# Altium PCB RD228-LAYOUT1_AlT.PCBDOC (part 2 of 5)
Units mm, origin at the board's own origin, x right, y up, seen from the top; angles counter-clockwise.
Board outline 130 x 73 mm, 4 copper layers (TOP, Mid-Layer 1, Mid-Layer 2, BOTTOM), stack 0.711 mm thick; 225 components, 171 nets, 818 pads, 538 vias.
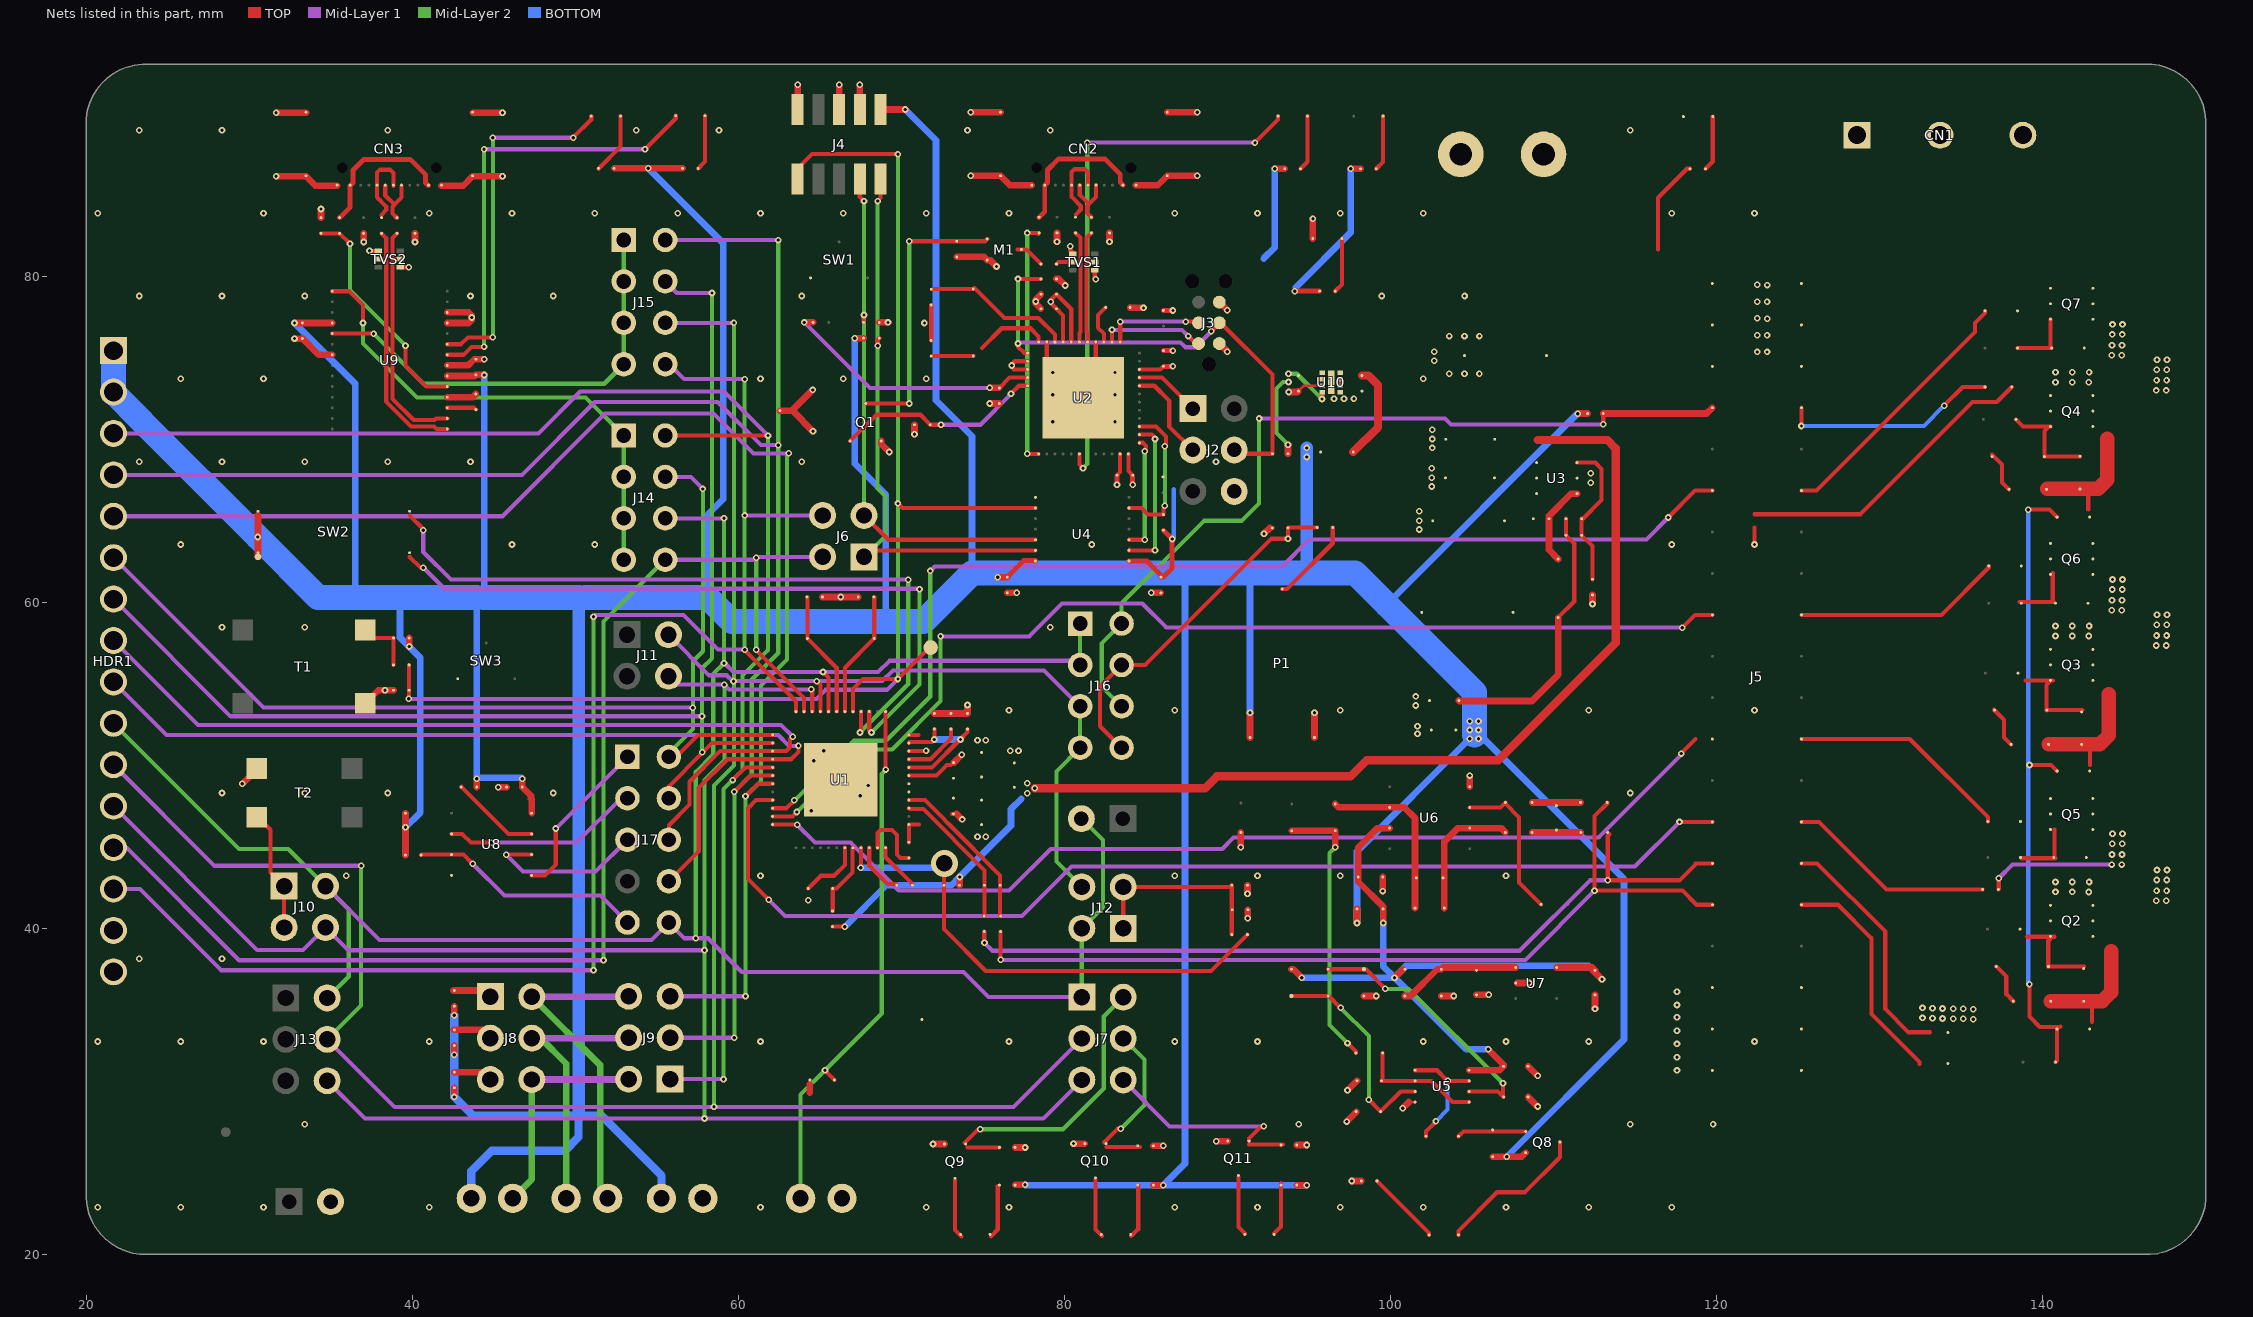
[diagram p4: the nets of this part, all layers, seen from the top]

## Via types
v1: diameter 0.406, hole 0.203, TOP to BOTTOM, tented both sides, 533 vias
v2: diameter 6, hole 4.2, TOP to BOTTOM, 4 vias
v3: diameter 1.651, hole 1, TOP to BOTTOM, 1 vias

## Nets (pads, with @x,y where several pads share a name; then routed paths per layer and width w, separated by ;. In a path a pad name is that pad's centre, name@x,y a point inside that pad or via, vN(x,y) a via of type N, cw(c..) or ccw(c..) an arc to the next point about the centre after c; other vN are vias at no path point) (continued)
GND: ?.2 C1.1 C2.1 C3.1 C4.1 C5.1 C6.1 C7.1 C8.1 C9.1 C10.1 C11.1 C12.1 C13.1 C15.1 C17.2 C18.2 C19.2 C22.1 C23.2 C24.1 C25.1 C26.1 C29.2 C30.2 C32.2 C33.2 C34.2 C35.2 C36.2 C37.2 C38.2 C40.1 C41.1 C42.2 C44.1 C46.1 C52.1 C53.1 C55.1 C57.1 C58.1 C59.1 C60.1 C61.1 CN2.1 CN2.2 CN2.3 CN2.4 CN2.A1B12 CN2.B1A12 CN3.1 CN3.2 CN3.3 CN3.4 CN3.A1B12 CN3.B1A12 D3.2 HDR1.15 HDR1.16 J2.6 J3.5 J4.3 J4.5 J4.9 J5.35 J5.37 J5.39 J18.2 LD1.1 LD3.1 P1.3 Q1.2 Q9.2 Q10.2 Q11.2 R5.1 R10.1 R17.1 R18.1 R21.2 R35.1 R36.1 R55.2 R58.1 R60.1 R61.1 R62.1 R65.2 R67.2 R69.2 R85.1 RT1.2 SW1.1 SW3.1 T1.1 T2.1 TB1.1 TB2.2 TB5.2 TP2.1 TP3.1 TVS1.1 TVS1.4 TVS2.1 TVS2.4 U1.19 U1.31 U1.34 U1.36 U1.49 U2.2 U2.3 U2.24 U2.41 U2.47 U2.49 U3.2 U4.9 U5.4 U6.4 U7.2 U8.4 U9.7 U9.18 U9.21 U9.25 U9.26 U10.3 U10.5 U10.9 | length 131.2
  TOP w0.152: C40.1@94.35,72.945 94.684,73.279 U10.3@95.815,73.279 ; 101.122,29.346 U5.4@101.508,29.346
  TOP w0.254: v1(37.377,81.553) 37.385,81.545 TVS2.1@37.922,81.545 ; TVS2.4@39.272,80.545 v1(39.79,80.545) ; C44.1@64.288,42.437 65.075,43.225 65.864,43.225 66.533,43.894 U1.19@66.533,44.942 ; U1.31@70.458,49.367 72.146,49.367 72.785,50.006 73.014,50.006 ; U1.34@70.458,50.867 71.487,50.867 v1(71.515,50.895) ; U1.36@70.458,51.867 71.039,51.867 ; C12.1@71.828,76.055 C13.1@71.828,78.228 ; C7.1@71.989,53.179 C7.1@72.023,53.179 ; C3.1@73.103,47.022 C3.1@73.192,47.022 73.381,47.022 ; C5.1@73.195,50.167 C5.1@73.225,50.167 ; U2.3@77.738,74.276 76.913,74.276 76.773,74.416 v1(76.773,74.517) 76.773,74.594 76.955,74.776 U2.2@77.738,74.776 ; U2.47@78.918,75.956 78.918,74.776 79.448,74.246 U2.49@81.168,72.526 81.918,73.276 U2.41@81.918,75.956 ; U2.24@83.918,69.096 83.918,68.055 C35.2@84.187,67.786 ; 92.597,64.561 C17.2@92.752,64.561 ; U6.4@104.856,48.686 U6.4@104.865,48.694 ; v1(122.319,63.538) 122.319,64.59 ; 122.319,65.399 128.817,65.399 135.694,72.276 137.175,72.276 RT1.2@138.096,73.197 RT1.2@138.088,73.204
  TOP w0.279: v1@80.354,81.807 80.354,81.579 80.503,81.43 TVS1.1@80.503,81.359 ; v1@81.853,79.876 TVS1.4@81.853,80.359
  TOP w0.305: v1(84.187,67.202) C35.2@84.187,67.786 ; C36.2@86.069,75.429 v1(86.653,75.429)
  TOP w0.406: v1(29.58,48.867) 29.584,48.867 30.469,49.752 T2.1@30.469,49.805 T2.1@30.469,50.059 ; v1(31.652,86.12) 33.487,86.12 34.062,85.544 CN3.B1A12@35.397,85.544 ; v1(31.652,90.02) CN3.4@33.487,90.02 ; v1(32.78,76.168) 33.26,76.168 C29.2@33.263,76.171 34.26,75.173 U9.7@35.097,75.173 ; R17.1@34.406,83.583 v1(34.406,84.116) ; v1(37.022,82.089) R61.1@37.022,82.623 ; T1.1@37.114,53.802 37.917,54.604 v1(38.335,54.604) C33.2@38.853,54.604 ; v1(40.171,82.089) R62.1@40.171,82.623 ; CN3.A1B12@41.797,85.544 43.131,85.544 43.707,86.12 v1(45.541,86.12) ; U9.18@42.147,72.572 43.708,72.572 C32.2@43.905,72.77 ; U9.21@42.147,74.523 43.428,74.523 43.808,74.903 C30.2@43.905,74.903 44.409,74.903 v1(44.413,74.898) ; U9.25@42.147,77.124 43.464,77.124 43.651,77.311 v1(43.651,77.464) 43.651,77.591 43.468,77.774 U9.26@42.147,77.774 ; CN3.1@43.707,90.02 v1(45.541,90.02) ; v1(45.272,48.66) C26.1@45.79,48.66 ; TP2.1@62.549,71.749 63.285,71.749 ; J4.9@63.641,90.215 v1(63.641,91.735) ; 64.383,29.927 64.383,30.445 ; v1(64.555,73.019) 63.285,71.749 ; v1(64.583,70.479) 63.313,71.749 63.285,71.749 ; C10.1@65.162,60.319 C9.1@67.352,60.319 ; J4.5@66.181,90.215 v1(66.181,91.735) ; J4.3@67.451,90.215 v1(67.451,91.735) ; R21.2@68.642,77.159 v1(69.176,77.159) ; Q1.2@68.761,69.888 68.761,69.703 v1(69.254,69.209) ; v1(70.806,70.301) R5.1@70.806,70.885 ; v1(71.942,26.774) Q9.2@72.643,26.774 ; C7.1@72.023,53.179 C6.1@73.039,53.179 C8.1@74.055,53.179 v1(74.055,53.697) ; C5.1@73.225,50.167 v1(73.699,50.641) ; 73.381,47.022 v1(73.725,46.679) ; v1(74.248,86.152) CN2.3@76.082,86.152 76.658,85.576 CN2.B1A12@77.992,85.576 ; v1(74.248,90.052) CN2.4@76.082,90.052 ; v1(75.427,72.183) C34.2@76.011,72.183 ; C18.2@76.493,60.575 v1(77.078,60.575) ; R65.2@76.973,26.562 v1(77.586,26.562) ; C37.2@78.553,77.997 78.246,78.305 v1(78.246,78.442) 78.246,78.579 C38.2@78.553,78.886 ; ?.2@79.513,79.826 79.643,79.826 v1(80.049,79.42) ; v1(79.541,82.115) R35.1@79.541,82.648 ; v1(80.553,26.799) Q10.2@81.254,26.799 ; v1(82.767,82.115) R36.1@82.767,82.648 ; C11.1@84.025,78.073 84.051,78.048 v1(84.85,78.048) ; CN2.A1B12@84.392,85.576 85.727,85.576 CN2.2@86.302,86.152 v1(88.137,86.152) ; v1(85.333,60.575) C19.2@85.917,60.575 ; R67.2@85.454,26.664 v1(86.067,26.664) ; CN2.1@86.302,90.052 v1(88.137,90.052) ; v1(89.316,26.952) Q11.2@90.017,26.952 ; J3.5@89.498,78.404 v1(89.994,77.908) ; v1(90.819,44.977) C55.1@90.819,45.881 ; v1(91.223,42.122) C46.1@91.223,42.641 ; v1(91.251,40.621) R85.1@91.251,41.139 ; v1(92.241,64.205) 92.597,64.561 ; v1(93.765,72.892) 94.296,72.892 C40.1@94.35,72.945 ; R69.2@94.245,26.715 v1(94.858,26.715) ; LD3.1@95.239,82.3 v1(95.239,83.512) ; P1.3@95.334,51.705 v1(95.334,53.226) ; v1(97.309,28.15) 97.892,28.733 C57.1@97.892,28.763 ; v1(97.36,30.068) C59.1@97.943,30.652 ; v1(97.626,24.505) R55.2@98.21,24.505 ; R60.1@98.363,35.851 v1(99.118,35.851) ; v1(99.519,42.285) C52.1@99.519,43.148 ; v1(100.75,28.975) 101.122,29.346 ; R58.1@103.113,35.851 v1(103.867,35.851) ; U6.4@104.865,48.694 v1(104.865,49.367) ; C61.1@105.272,35.921 v1(106.026,35.921) ; U7.2@107.761,36.646 v1(108.516,36.646) ; C58.1@108.435,29.661 v1(109.018,29.078) ; C53.1@108.435,31.541 v1(109.018,30.957) ; v1(112.384,59.887) R10.1@112.384,60.448 ; v1(112.536,35.058) C60.1@112.536,35.921
  other v1: 20.719,22.898 25.799,22.898 30.879,22.898 41.039,22.898 61.359,22.898 71.519,22.898 76.599,22.898 86.759,22.898 91.839,22.898 96.919,22.898 101.999,22.898 107.079,22.898 112.159,22.898 117.239,22.898 33.419,27.978 94.379,27.978 114.699,27.978 119.779,27.978 117.565,31.287 117.565,32.099 117.565,32.912 20.719,33.058 25.799,33.058 30.879,33.058 41.039,33.058 61.359,33.058 76.599,33.058 86.759,33.058 91.839,33.058 101.999,33.058 107.079,33.058 112.159,33.058 122.319,33.058 117.565,33.725 117.565,34.538 117.565,35.3 117.565,36.113 23.259,38.138 28.339,38.138 64.288,41.726 35.959,43.218 61.359,43.218 86.759,43.218 91.839,43.218 96.919,43.218 107.079,43.218 74.665,45.612 75.173,45.612 64.479,47.212 67.476,48.127 28.339,48.298 33.419,48.298 38.499,48.298 48.659,48.298 114.699,48.298 67.959,48.762 64.632,50.286 65.241,50.895 76.671,50.895 77.179,50.895 74.665,51.53 75.173,51.53 101.65,51.937 101.65,52.394 76.599,53.378 86.759,53.378 96.919,53.378 112.159,53.378 122.319,53.378 101.538,53.664 101.538,54.223 28.339,58.458 33.419,58.458 79.139,58.458 66.283,60.319 25.799,63.538 46.119,63.538 51.199,63.538 81.679,63.538 117.239,63.538 101.754,64.459 101.754,65.002 101.754,65.577 102.53,67.097 112.282,67.329 102.53,67.64 112.282,67.913 102.53,68.214 23.259,68.618 28.339,68.618 33.419,68.618 38.499,68.618 43.579,68.618 63.899,68.618 89.299,68.618 102.554,69.463 102.554,70.006 102.554,70.58 79.287,71.063 83.097,71.063 96.534,72.485 97.144,72.485 97.753,72.485 79.287,72.714 83.097,72.714 25.799,73.698 30.879,73.698 61.359,73.698 66.439,73.698 71.519,73.698 101.999,73.698 103.595,74.009 104.535,74.009 105.449,74.009 79.287,74.086 83.097,74.086 102.679,74.804 102.679,75.363 103.595,76.321 104.535,76.321 105.449,76.321 71.413,77.124 23.259,78.778 28.339,78.778 33.419,78.778 43.579,78.778 48.659,78.778 63.899,78.778 99.459,78.778 104.539,78.778 81.919,79.81 80.354,81.833 20.719,83.858 30.879,83.858 41.039,83.858 46.119,83.858 51.199,83.858 56.279,83.858 61.359,83.858 66.439,83.858 71.519,83.858 76.599,83.858 86.759,83.858 91.839,83.858 96.919,83.858 101.999,83.858 117.239,83.858 122.319,83.858 23.259,88.938 28.339,88.938 38.499,88.938 53.739,88.938 58.819,88.938 74.059,88.938 79.139,88.938 114.699,88.938
HALL-U: J8.6 J9.2 TB3.2 | length 13.7
  Mid-Layer 1 w0.406: J8.6@47.334,30.728 53.252,30.728 J9.2@53.278,30.753
  Mid-Layer 2 w0.406: TB3.2@46.166,23.438 47.334,24.606 J8.6@47.334,30.728
HALL-V: J8.4 J9.4 TB4.1 | length 17
  Mid-Layer 1 w0.406: J8.4@47.334,33.268 53.252,33.268 J9.4@53.278,33.293
  Mid-Layer 2 w0.406: J8.4@47.334,33.268 47.868,33.268 49.442,31.693 TB4.1@49.442,23.438
HALL-W: J8.2 J9.6 TB4.2 | length 20.2
  Mid-Layer 1 w0.406: J8.2@47.334,35.808 53.252,35.808 J9.6@53.278,35.833
  Mid-Layer 2 w0.406: J8.2@47.334,35.808 51.525,31.617 51.525,23.895 TB4.2@51.982,23.438
I_LIMIT_H: C57.2 pad.@93.918,35.851 R57.1 R59.2 U5.3 | length 13.3
  TOP w0.254: R57.1@93.918,35.851 R59.2@96.178,35.851 96.211,35.851 v1(96.94,35.122) ; v1(98.668,29.487) C57.2@99.392,28.763 100.626,29.996 U5.3@101.508,29.996
  Mid-Layer 2 w0.254: v1(96.94,35.122) 98.668,33.395 v1(98.668,29.487)
I_LIMIT_L: C58.2 pad.@98.363,37.492 R59.1 R60.2 U5.6 | length 16.7
  TOP w0.254: R59.1@96.178,37.492 R60.2@98.363,37.492 98.483,37.492 v1(99.684,36.29) ; U5.6@104.818,29.996 106.599,29.996 C58.2@106.897,29.698 ; v1(106.897,30.499) C58.2@106.897,29.698 ; C58.2@106.935,29.661 C58.2@106.897,29.698
  Mid-Layer 2 w0.254: v1(99.684,36.29) 101.106,36.29 v1(106.897,30.499)
I_MEAS: R46.2 R47.1 R50.1 | length 17.1
  TOP w0.254: v1(97.36,32.963) 97.873,32.45 R50.1@97.873,32.353
  TOP w0.406: R47.1@93.943,45.986 R46.2@96.61,45.986 v1(96.61,44.964)
  Mid-Layer 2 w0.254: v1(96.61,44.964) 96.255,44.608 96.255,34.068 v1(97.36,32.963)
IO0: HDR1.3 J9.1 J14.2 U1.5 | length 95.3
  TOP w0.254: J14.2@55.513,70.225 v1@61.838,70.225 ; v1(59.653,49.092) 60.429,49.867 U1.5@62.108,49.867
  Mid-Layer 1 w0.254: HDR1.3@21.68,70.352 47.741,70.352 50.306,72.917 59.12,72.917 v1(61.817,70.22) ; J9.1@55.818,30.753 v1(59.094,30.753)
  Mid-Layer 2 w0.254: v1(59.094,30.753) 59.094,48.533 v1(59.653,49.092) 60.263,49.702 60.263,55.508 61.812,57.057 v1@61.812,70.225
IO1: HDR1.4 J9.3 J15.2 U1.6 | length 107.4
  TOP w0.254: v1@59.755,48.367 60.755,49.367 U1.6@62.108,49.367
  Mid-Layer 1 w0.254: HDR1.4@21.68,67.812 46.725,67.812 51.195,72.282 58.739,72.282 61.385,69.636 v1(62.452,69.636) ; J15.2@55.513,82.214 v1@62.447,82.214 ; J9.3@55.818,33.293 v1(59.755,33.293)
  Mid-Layer 2 w0.254: v1(59.755,33.293) v1(59.755,48.381) 60.822,49.448 60.822,55.264 62.447,56.89 62.447,69.636 v1@62.447,82.214
  other v1: 62.452,82.209
IO2: HDR1.5 J9.5 U1.7 | length 86
  TOP w0.254: v1(60.441,48.101) 61.207,48.867 U1.7@62.108,48.867
  Mid-Layer 1 w0.254: HDR1.5@21.68,65.272 45.531,65.272 51.83,71.571 58.485,71.571 60.928,69.128 v1(63.087,69.128) ; J9.5@55.818,35.833 v1(60.441,35.833)
  Mid-Layer 2 w0.254: v1(60.441,35.833) v1(60.441,48.101) 61.38,49.041 61.38,54.883 62.981,56.483 62.981,69.031 v1@63.082,69.133
IO3: HDR1.6 J14.4 J17.2 U1.1 | length 66.2
  TOP w0.254: J17.2@55.742,50.514 56.173,50.514 57.526,51.867 U1.1@62.108,51.867
  Mid-Layer 1 w0.254: HDR1.6@21.68,62.732 30.875,53.537 v1(57.215,53.537) ; J14.4@55.513,67.685 57.088,67.685 v1(57.824,66.948)
  Mid-Layer 2 w0.254: J17.2@55.742,50.514 55.742,50.743 57.215,52.216 v1(57.215,53.537) 57.215,56.382 57.824,56.991 v1@57.824,66.923
IO4: HDR1.7 J15.4 J17.4 U1.2 | length 79.3
  TOP w0.254: J17.4@56.148,47.974 J17.4@55.742,47.974 55.742,48.711 57.805,50.774 58.398,51.367 U1.2@62.108,51.367
  Mid-Layer 1 w0.254: HDR1.7@21.68,60.192 28.868,53.004 v1(57.774,53.004) ; J15.4@55.513,79.674 56.224,78.962 v1(58.383,78.962)
  Mid-Layer 2 w0.254: v1@57.774,50.794 v1(57.774,53.004) 57.774,55.95 58.383,56.56 v1(58.383,78.962)
  other v1: 57.786,50.794
IO5: HDR1.8 J17.6 U1.3 | length 56
  TOP w0.254: J17.6@55.742,45.434 55.742,46.323 57.012,47.593 57.012,48.99 58.889,50.867 U1.3@62.108,50.867 62.939,50.867 63.179,51.107 63.179,51.602 v1(63.336,51.759)
  Mid-Layer 1 w0.254: HDR1.8@21.68,57.652 26.862,52.47 62.625,52.47 v1(63.336,51.759) v1@63.362,51.734
IO6: HDR1.9 J17.8 U1.4 | length 57.5
  TOP w0.254: J17.8@55.742,42.894 57.57,44.723 57.57,48.609 59.328,50.367 U1.4@62.108,50.367 63.243,50.367 63.687,50.812 v1(63.687,51.192)
  Mid-Layer 1 w0.254: HDR1.9@21.68,55.112 24.931,51.861 62.447,51.861 63.116,51.192 v1(63.687,51.192)
IO7: HDR1.10 J7.1 J10.2 J12.2 J13.2 J14.6 J16.1 J16.3 J17.10 J33.2 U1.44 | length 145.7
  TOP w0.254: v1(65.19,55.721) 65.533,55.379 U1.44@65.533,53.292
  Mid-Layer 1 w0.254: J10.2@34.685,42.59 37.987,39.288 54.675,39.288 J17.10@55.742,40.354 56.707,39.389 v1(57.393,39.389) 58.155,39.389 60.212,37.332 73.801,37.332 75.35,35.782 J7.1@81.065,35.782 ; J14.6@55.488,65.145 J14.6@55.513,65.145 v1(59.12,65.145) ; v1(59.12,56.255) 59.166,56.255 59.7,55.721 v1(65.19,55.721) 68.575,55.721 69.261,56.407 80.71,56.407 J16.3@80.964,56.153 ; J12.2@80.735,39.389 J12.2@81.294,39.948
  Mid-Layer 2 w0.254: HDR1.10@21.68,52.572 29.376,44.876 32.399,44.876 J10.2@34.685,42.59 36.107,41.167 36.107,37.052 J13.2@34.787,35.732 ; v1(57.393,39.389) 57.393,49.6 58.459,50.667 58.459,55.594 v1(59.12,56.255) v1(59.12,65.145) ; J16.3@80.964,56.153 J16.1@80.964,58.693 ; J33.2@81.04,46.73 82.361,45.409 82.361,41.294 J12.2@81.065,39.999 J7.1@81.065,35.782
IO8: HDR1.11 J7.3 J11.2 J12.4 J13.4 J15.6 J16.5 J16.7 U1.45 | length 173.7
  TOP w0.254: v1(64.809,55.163) 65.033,54.939 U1.45@65.033,53.292
  Mid-Layer 1 w0.254: HDR1.11@21.68,50.032 27.878,43.834 v1(36.869,43.834) ; J13.4@34.787,33.192 38.927,29.051 v1(58.51,29.051) 76.874,29.051 J7.3@81.065,33.242 ; J15.6@55.538,77.134 v1(59.729,77.134) ; J11.2@55.716,58.007 58.205,55.518 59.292,55.518 59.648,55.163 v1(59.704,55.163) v1(64.809,55.163) 68.823,55.163 69.483,55.823 78.754,55.823 J16.5@80.964,53.613
  Mid-Layer 2 w0.254: J13.4@34.787,33.192 36.869,35.274 v1(36.869,43.834) ; v1(58.51,29.051) 58.51,48.762 59.729,49.981 59.729,55.163 v1(59.729,77.134) ; J16.5@80.964,53.613 J16.7@80.964,51.073 79.516,49.625 79.516,44.088 J12.4@81.065,42.539
IO9: HDR1.12 J7.5 J10.4 J11.4 J13.6 U1.46 | length 126.8
  TOP w0.254: U1.46@64.533,53.292 v1@64.533,54.655
  Mid-Layer 1 w0.254: HDR1.12@21.68,47.492 30.494,38.678 33.313,38.678 J10.4@34.685,40.05 36.082,38.653 v1(57.926,38.653) ; J13.6@34.787,30.652 37.098,28.34 v1(57.926,28.34) 78.703,28.34 J7.5@81.065,30.702 ; J11.4@55.716,55.467 56.237,54.947 v1(59.145,54.947) 59.437,54.655 v1(64.479,54.655)
  Mid-Layer 2 w0.254: v1(57.926,28.34) v1(57.926,38.653) 57.926,49.092 59.145,50.311 v1(59.145,54.947)
IO10: HDR1.13 J6.2 J14.8 U1.47 | length 79.3
  TOP w0.254: v1@61.088,57.08 64.033,54.136 U1.47@64.033,53.292
  Mid-Layer 1 w0.254: HDR1.13@21.68,44.952 22.468,44.952 29.376,38.043 v1(51.728,38.043) ; J14.8@55.513,62.605 60.974,62.605 v1(61.101,62.732) ; v1@61.203,62.732 61.253,62.783 J6.2@65.169,62.783
  Mid-Layer 2 w0.254: v1(51.728,38.043) 51.728,58.82 J14.8@55.513,62.605 ; v1(61.101,57.093) v1(61.101,62.732)
IO11: HDR1.14 J6.4 J15.8 U1.48 | length 95.1
  TOP w0.254: v1(60.39,57.093) 60.39,57.068 63.533,53.925 U1.48@63.533,53.292
  Mid-Layer 1 w0.254: HDR1.14@21.68,42.412 23.306,42.412 28.284,37.433 v1(51.119,37.433) ; v1(51.119,59.1) 51.246,59.227 56.631,59.227 58.764,57.093 v1(60.39,57.093) ; J15.8@55.513,74.594 55.767,74.594 56.681,73.679 v1(60.39,73.679) ; v1(60.39,65.323) J6.4@65.169,65.323
  Mid-Layer 2 w0.254: v1(51.119,37.433) v1(51.119,59.1) ; v1(60.39,57.093) v1(60.39,65.323) v1(60.39,73.679)
LED1: J7.2 Q9.1 R65.1 | length 18
  TOP w0.254: 73.889,26.853 74.69,27.654 v1@74.868,27.654 ; 74.055,26.562 R65.1@76.013,26.562
  Mid-Layer 2 w0.254: v1(74.842,27.68) 79.922,27.68 82.412,30.169 82.412,34.589 J7.2@83.605,35.782
LED2: J7.4 Q10.1 R67.1 | length 10.1
  TOP w0.254: 82.423,26.879 83.25,27.705 v1(83.453,27.705) ; 82.589,26.588 84.624,26.588
  Mid-Layer 2 w0.254: v1(83.453,27.705) 84.901,29.153 84.901,31.947 J7.4@83.605,33.242
LED3: J7.6 Q11.1 R69.1 | length 13.2
  TOP w0.254: Q11.1@91.317,26.952 91.317,27.111 92.064,27.858 v1(92.216,27.858) ; 91.327,26.74 93.387,26.74
  Mid-Layer 1 w0.254: J7.6@83.605,30.702 86.45,27.858 v1(92.216,27.858)
LIN_BUS: C15.2 TB2.1 U1.37 | length 33.5
  TOP w0.254: v1(65.317,31.296) 65.317,31.275 C15.2@65.89,30.702 ; v1@69.033,49.702 U1.37@69.033,53.292
  Mid-Layer 2 w0.254: TB2.1@63.819,23.438 63.819,29.798 v1(65.317,31.296) 68.797,34.776 68.797,49.473 v1@69.047,49.722
  BOTTOM w0.508: TB2.1@63.819,23.438 TB2.1@63.819,24.048
  other v1: 69.033,49.736
LS_SOURCE: J5.30 Q5.4 Q6.4 Q7.4 R40.1 R41.1 R42.1 R43.2 R89.1 | length 22.9
  TOP w0.254: J5.30@125.197,43.987 126.153,43.987 130.341,39.798 130.341,35.046 131.764,33.623 133.085,33.623 ; R89.1@137.273,42.386 137.301,42.414 v1(137.301,43.072)
  Mid-Layer 1 w0.254: v1(137.301,43.072) 138.139,43.911 v1(144.231,43.911)
  other v1: 135.122,34.448 135.737,34.432 133.852,34.473 134.507,34.464 132.622,34.505 133.237,34.489 135.122,35.061 135.737,35.045 133.852,35.087 134.507,35.077 133.237,35.103 132.622,35.119 144.845,43.911 144.247,44.525 144.861,44.525 144.257,45.181 144.87,45.181 144.273,45.795 144.886,45.795 144.231,59.506 144.845,59.506 144.247,60.121 144.861,60.121 144.257,60.776 144.87,60.776 144.273,61.391 144.886,61.391 144.231,75.152 144.845,75.152 144.247,75.767 144.861,75.767 144.257,76.422 144.87,76.422 144.273,77.037 144.886,77.037
M_U: J5.24 R70.1 | length 13.7
  TOP w0.254: J5.24@125.197,51.607 131.84,51.607 136.631,46.815 R70.1@136.631,46.552
M_V: J5.18 R71.1 | length 12.8
  TOP w0.254: J5.18@125.197,59.227 133.796,59.227 136.682,62.113 R71.1@136.682,62.224
M_W: J5.12 R72.1 | length 16.2
  TOP w0.254: J5.12@125.197,66.847 126.125,66.847 135.853,76.575 135.853,77.134 136.453,77.734 R72.1@136.453,77.87
MD0: SW2.2 U1.40 | length 44.9
  TOP w0.254: 39.843,65.323 40.679,64.486 v1(40.679,64.408) ; v1(67.459,52.013) 67.533,52.087 U1.40@67.533,53.292
  Mid-Layer 1 w0.254: v1(40.679,64.408) 40.679,63.087 42.381,61.386 v1(70.423,61.386)
  Mid-Layer 2 w0.254: v1(67.459,52.013) 67.662,52.216 67.662,52.223 70.423,54.984 v1(70.423,61.386)
MD1: SW2.1 U1.39 | length 43.5
  TOP w0.254: 39.867,62.783 39.843,62.783 40.503,62.122 v1(40.679,62.122) ; U1.39@68.033,53.292 68.033,52.116 v1@68.17,51.978
  Mid-Layer 1 w0.254: v1(40.679,62.122) 41.975,60.827 v1@71.109,60.827
  Mid-Layer 2 w0.254: v1(68.17,52.013) 71.109,54.951 v1(71.109,60.801)
NetC16_1: C16.1 D3.1 L1.1 U3.6
NetC16_2: C16.2 D2.1 U3.1 | length 5.2
  TOP w0.406: D2.1@110.275,62.652 109.714,63.214 C16.2@109.714,65.119 109.714,65.295 111.078,66.659 U3.1@111.439,66.659
NetC21_1: C21.1 R9.1 R10.2 U3.3 | length 9.3
  TOP w0.254: U3.3@111.439,68.559 112.551,68.559 112.942,68.167 112.942,66.262 111.8,65.12 C21.1@111.721,65.12 R9.1@111.721,64.103 112.384,63.44 R10.2@112.384,61.408
NetC27_1: C27.1 U1.25 | length 1.7
  TOP w0.254: C27.1@70.458,45.279 U1.25@70.458,46.367 71.065,46.367
NetC27_2: C27.2 U1.23 | length 4.3
  TOP w0.254: U1.23@68.533,44.942 68.533,45.856 68.717,46.04 69.426,46.04 69.737,45.729 69.737,44.52 69.938,44.319 C27.2@70.423,44.319
NetC28_1: C28.1 U1.24 | length 2.9
  TOP w0.254: U1.24@69.033,44.942 69.033,44.361 70.649,42.745 C28.1@70.649,42.717
NetC28_2: C28.2 U1.22 | length 3.2
  TOP w0.254: U1.22@68.033,44.942 68.033,43.837 69.153,42.717 C28.2@69.689,42.717
NetC32_1: C32.1 U9.17 | length 1.8
  TOP w0.254: U9.17@42.147,71.922 43.793,71.922 C32.1@43.905,71.81
NetC41_2: C41.2 FP2.2 U10.6 U10.7 U10.8 | length 6.4
  TOP w0.203: U10.6@96.915,73.279 U10.7@96.915,73.679
  TOP w0.508: FP2.2@97.712,69.209 99.226,70.723 99.226,73.324 98.645,73.905 C41.2@98.245,73.905
NetC44_2: C44.2 R81.1 U1.20 | length 4.5
  TOP w0.254: R81.1@65.775,41.063 65.788,41.076 C44.2@65.788,42.437 66.012,42.437 66.994,43.419 66.994,44.904 U1.20@67.033,44.942
NetC45_1: C45.1 R83.1 U1.28 | length 10
  TOP w0.254: U1.28@70.458,47.867 71.439,47.867 72.637,46.67 72.637,46.655 72.859,46.433 72.874,46.433 76.059,43.247 C45.1@76.059,42.641 76.059,40.786 R83.1@76.087,40.758
NetC45_2: C45.2 R82.1 U1.27 | length 9
  TOP w0.254: U1.27@70.458,47.367 70.516,47.309 71.348,47.309 75.099,43.558 C45.2@75.099,42.641 75.099,40.772 R82.1@75.085,40.758
NetC54_1: C54.1 R48.2 R49.1 | length 3
  TOP w0.406: R49.1@108.683,47.72 110.174,47.72 R48.2@111.647,47.72
NetC54_2: C54.2 R44.2 R45.1 | length 3
  TOP w0.406: R45.1@108.683,45.88 110.174,45.88 R44.2@111.672,45.88
NetC56_1: C56.1 R46.1 R54.2 U6.6 | length 10.8
  TOP w0.406: R46.1@96.61,47.626 96.821,47.416 U6.6@99.946,47.416 100.843,47.416 101.501,46.757 101.501,43.098 C56.1@101.501,41.243
NetC56_2: C56.2 R45.2 R54.1 U6.2 | length 8.3
  TOP w0.406: C56.2@103.301,41.243 103.301,43.098 103.301,45.318 104.129,46.146 U6.2@104.856,46.146 106.776,46.146 R45.2@107.042,45.88
NetC59_2: C59.2 R50.2 U5.2 U5.5 | length 7.6
  TOP w0.254: R50.2@99.513,32.353 99.513,30.722 C59.2@99.443,30.652 99.448,30.646 U5.2@101.508,30.646 102.508,30.646 103.808,29.346 U5.5@104.818,29.346
NetC61_2: C61.2 R56.1 R58.2 U7.1 | length 7.5
  TOP w0.406: R56.1@100.877,35.851 101.226,35.851 102.866,37.492 R58.2@103.113,37.492 103.217,37.596 105.272,37.596 U7.1@107.674,37.596
NetCN2_A4B9: CN2.A4B9 CN2.B4A9 R86.2 | length 9
  TOP w0.305: R86.2@78.449,83.608 78.792,83.951 CN2.B4A9@78.792,85.576 78.958,85.741 78.958,86.507 79.643,87.192 82.475,87.192 83.423,86.244 83.423,85.746 CN2.A4B9@83.592,85.576
NetDZ1_1: DZ1.1 DZ4.1 | length 2.6
  TOP w0.254: DZ1.1@137.149,37.658 137.761,37.046 137.761,35.96 DZ4.1@138.19,35.532
NetDZ1_2: DZ1.2 Q2.3 R27.2 R30.2 | length 5.8
  TOP w0.254: 139.032,39.487 140.603,39.487 ; DZ1.2@140.333,37.642 140.333,39.217 140.603,39.487 ; DZ1.2@140.349,37.658 142.518,37.658 ; 140.71,39.487 140.603,39.487
NetDZ2_1: DZ2.1 DZ5.1 | length 2.6
  TOP w0.254: DZ2.1@137.015,53.406 137.627,52.794 137.627,51.708 DZ5.1@138.056,51.28
NetDZ2_2: DZ2.2 Q3.3 R28.2 R31.2 | length 5.8
  TOP w0.254: 138.93,55.209 Q3.3@140.501,55.209 ; DZ2.2@140.231,53.365 140.231,54.94 Q3.3@140.501,55.209 ; DZ2.2@140.247,53.381 142.416,53.381 ; 140.608,55.209 Q3.3@140.501,55.209
NetDZ3_1: DZ3.1 DZ6.1 | length 2.6
  TOP w0.254: 136.888,69.05 137.5,68.438 137.5,67.352 DZ6.1@137.929,66.924
NetDZ3_2: DZ3.2 Q4.3 R29.2 R32.2 | length 6.5
  TOP w0.254: R29.2@138.352,71.215 138.793,70.774 140.365,70.774 ; Q4.3@140.472,70.774 140.365,70.774 ; R32.2@142.279,68.945 140.111,68.945 DZ3.2@140.095,68.929 140.095,70.504 140.365,70.774
NetJ8_1: J8.1 R74.2 | length 2.4
  TOP w0.406: R74.2@42.534,36.186 R74.2@42.584,36.186 44.416,36.186 J8.1@44.794,35.808
NetJ8_3: J8.3 R75.2 | length 2.4
  TOP w0.406: R75.2@42.559,33.773 R75.2@42.584,33.773 44.289,33.773 J8.3@44.794,33.268
NetJ8_5: J8.5 R76.2 | length 2.4
  TOP w0.406: R76.2@42.584,31.182 44.34,31.182 J8.5@44.794,30.728
NetLD1_2: LD1.2 R3.1 | length 3.4
  TOP w0.254: R3.1@119.315,86.582 119.761,87.028 LD1.2@119.761,89.783
NetLD2_2: LD2.2 R22.2 | length 3.4
  TOP w0.254: R22.2@94.474,86.582 94.905,87.013 LD2.2@94.905,89.808
NetLD3_2: LD3.2 R23.1 | length 3.4
  TOP w0.254: R23.1@96.608,79.074 97.028,79.494 LD3.2@97.028,82.3
NetLD4_2: LD4.2 R25.2 | length 3.4
  TOP w0.254: R25.2@99.122,86.582 99.542,87.002 LD4.2@99.542,89.808
NetLD5_1: LD5.1 R55.1 | length 4.6
  TOP w0.254: R55.1@99.17,24.505 102.365,21.31 LD5.1@102.365,21.203
NetLD5_2: LD5.2 Q8.3 | length 9.3
  TOP w0.254: LD5.2@104.165,21.203 104.165,21.442 106.542,23.819 108.243,23.819 110.386,25.961 Q8.3@110.386,26.892
NetLD6_2: LD6.2 R11.1 | length 3.8
  TOP w0.254: R11.1@51.426,86.582 52.781,87.937 LD6.2@52.781,89.808
NetLD7_2: LD7.2 R12.1 | length 3.4
  TOP w0.254: R12.1@57.542,86.608 57.962,87.028 LD7.2@57.962,89.834
NetLD8_1: LD8.1 Q9.3 | length 3.6
  TOP w0.254: 73.293,24.574 73.293,21.497 73.688,21.101
NetLD8_2: LD8.2 R64.1 | length 3.3
  TOP w0.254: 75.488,21.101 75.912,21.525 75.912,24.2
NetLD9_1: LD9.1 Q10.3 | length 3.6
  TOP w0.254: 81.904,24.599 81.904,21.522 82.299,21.127
NetLD9_2: LD9.2 R66.1 | length 3.3
  TOP w0.254: 84.099,21.127 84.522,21.55 R66.1@84.522,24.225
NetLD10_1: LD10.1 Q11.3 | length 3.6
  TOP w0.254: 90.667,24.752 90.667,21.674 LD10.1@91.062,21.279
NetLD10_2: LD10.2 R68.1 | length 3.3
  TOP w0.254: LD10.2@92.862,21.279 93.285,21.702 R68.1@93.285,24.251 93.285,24.378
NetM1_1: M1.1 Q1.3 R1.2 | length 17.4
  TOP w0.254: Q1.3@67.811,72.188 v1(70.481,72.188) ; v1(70.481,82.137) R1.2@73.395,82.137 75.121,82.137 M1.1@75.263,82.279
  Mid-Layer 2 w0.254: v1(70.481,72.188) v1@70.481,82.112
NetM1_3: M1.3 R4.2 | length 1.8
  TOP w0.254: 77.113,81.629 M1.3@77.363,81.629 77.664,81.629 R4.2@78.553,80.74
NetP1_2: P1.2 R6.2 | length 5.2
  TOP w0.254: P1.2@93.359,60.805 93.642,60.805 96.453,63.616 R6.2@96.453,64.586
NetQ5_3: Q5.3 R37.2 R40.2 | length 3.8
  TOP w0.254: R37.2@138.692,44.297 140.781,44.297 ; R40.2@140.71,44.368 140.71,46.065
NetQ6_3: Q6.3 R38.2 R41.2 | length 3.8
  TOP w0.254: 138.59,60.02 140.679,60.02 ; 140.608,60.091 140.608,61.787
NetQ7_3: Q7.3 R39.2 R42.2 | length 3.9
  TOP w0.254: R39.2@138.453,75.584 R42.2@140.543,75.584 140.472,75.655 Q7.3@140.472,77.352
NetQ8_1: Q8.1 R52.1 R53.2 | length 4.2
  TOP w0.254: R53.2@104.173,27.248 104.467,27.542 106.262,27.542 Q8.1@108.286,27.542
NetR24_1: R24.1 R26.2 T1.2 | length 3.6
  TOP w0.254: T1.2@37.114,58.302 37.612,57.804 R24.1@38.853,57.804 R26.2@38.853,56.153
NetR49_2: R49.2 R51.2 U6.3 | length 9.5
  TOP w0.254: U6.3@104.856,47.416 106.738,47.416 R49.2@107.042,47.72 107.042,47.652 107.888,46.806 107.888,42.818 R51.2@109.234,41.472
NetR73_2: R73.2 U8.7 | length 5.4
  TOP w0.254: R73.2@43.015,48.679 45.904,45.79 ; 46.031,45.79 U8.7@47.325,45.79
NetR77_2: R77.2 R78.2 R79.2 R80.2 | length 39.2
  TOP w0.254: v1(139.111,65.678) 140.416,65.678 R77.2@140.873,65.221 ; v1(139.181,36.57) 139.181,34.585 139.812,33.954 141.06,33.954 141.086,33.979 ; v1(139.187,50.018) 140.506,50.018 R79.2@140.873,49.651 ; R78.2@140.79,31.795 140.873,31.877 R80.2@140.873,33.827
  BOTTOM w0.254: v1(139.111,65.678) 139.111,50.018 139.111,36.64 v1(139.181,36.57)
OC_OUT: R53.1 U5.1 U5.7 | length 7.5
  TOP w0.254: U5.1@101.508,31.296 102.849,31.296 v1(103.499,30.646) U5.7@104.818,30.646 ; R53.1@102.173,27.248 102.173,27.553 v1(102.782,28.162)
  BOTTOM w0.254: v1(102.782,28.162) 103.499,28.879 v1(103.499,30.646)
P_USB-D_N: R34.2 TVS1.5 U2.42 | length 7.3
  TOP w0.254: U2.42@81.418,75.956 81.418,76.518 81.359,76.577 81.359,80.867 ; R34.2@81.65,82.648 81.359,82.357 81.359,80.867 ; TVS1.5@81.853,80.859 81.367,80.859 81.359,80.867
P_USB-D_P: R4.1 R33.2 TVS1.2 U2.43 | length 8.4
  TOP w0.254: R4.1@79.513,80.74 79.632,80.859 TVS1.2@80.503,80.859 80.96,80.859 80.978,80.842 ; R33.2@80.684,82.648 80.978,82.355 80.978,80.859 80.978,76.577 80.918,76.518 U2.43@80.918,75.956
P_USB_N: CN2.A7 CN2.B7 R34.1 | length 3.7
  TOP w0.254: CN2.A7@80.942,85.576 80.942,84.978 81.51,84.411 ; R34.1@81.65,83.608 81.383,83.875 81.383,84.284 81.51,84.411 ; CN2.B7@81.942,85.576 81.942,84.843 81.51,84.411
P_USB_P: CN2.A6 CN2.B6 R33.1 | length 4.9
  TOP w0.254: 80.71,83.786 81.002,84.078 81.002,84.309 80.442,84.869 CN2.B6@80.442,85.576 80.442,86.376 80.624,86.557 81.243,86.557 81.442,86.358 CN2.A6@81.442,85.576
P_X1: C13.2 U2.46 Y2.1 | length 8.9
  TOP w0.254: 71.942,79.209 Y2.1@74.411,79.209 ; 74.478,79.276 76.313,77.441 78.392,77.441 79.416,76.417 79.416,76.07
P_X2: C12.2 U2.48 Y2.2 | length 7
  TOP w0.254: 71.952,75.109 Y2.2@74.411,75.109 ; 74.946,75.594 76.155,76.804 77.92,76.804 78.418,76.306 U2.48@78.418,75.956
PHASE_U: CN1.1 DZ4.2 Q2.4 Q5.1 Q5.2 Q5.5 Q5.6 R30.1 R70.2 R80.1 | length 7.7
  TOP w0.254: 143.013,34.27 143.013,35.509
  TOP w0.508: 142.991,35.532 143.013,35.509
  TOP w0.889: DZ4.2@140.49,35.532 142.991,35.532 143.631,35.532 144.184,36.085 144.184,38.602
  other v1: 146.962,41.696 147.576,41.696 146.978,42.311 147.592,42.311 146.988,42.966 147.601,42.966 147.004,43.581 147.617,43.581
PHASE_V: CN1.2 DZ5.2 Q3.4 Q6.1 Q6.2 Q6.5 Q6.6 R31.1 R71.2 R79.1 | length 7.7
  TOP w0.254: 142.886,50.018 142.886,51.257
  TOP w0.889: DZ5.2@140.363,51.28 143.504,51.28 144.057,51.833 144.057,54.35
  other v1: 146.962,57.342 147.576,57.342 146.978,57.957 147.592,57.957 146.988,58.612 147.601,58.612 147.004,59.227 147.617,59.227
PHASE_W: CN1.3 DZ6.2 Q4.4 Q7.1 Q7.2 Q7.5 Q7.6 R32.1 R72.2 R77.1 | length 7.7
  TOP w0.254: 142.785,65.685 142.785,66.924
  TOP w0.889: DZ6.2@140.261,66.947 143.403,66.947 143.956,67.5 143.956,70.017
  other v1: 146.962,72.988 147.576,72.988 146.978,73.603 147.592,73.603 146.988,74.258 147.601,74.258 147.004,74.873 147.617,74.873
POT: C17.1 J16.4 J16.8 R6.1 | length 22
  TOP w0.254: J16.8@83.504,51.073 82.183,52.394 82.183,54.832 J16.4@83.504,56.153 84.952,56.153 92.694,63.895 v1(93.712,63.895) C17.1@93.712,64.561 93.737,64.586 R6.1@95.493,64.586
PROG_RXD: J2.3 U2.32 | length 5.8
  TOP w0.254: U2.32@84.598,73.276 85.508,73.276 86.425,72.358 86.425,70.784 J2.3@87.873,69.336
PROG_TXD: J2.1 U2.33 | length 4.1
  TOP w0.254: U2.33@84.598,73.776 85.973,73.776 J2.1@87.873,71.876
PUCTRL: Q1.1 R5.2 U2.5 | length 12.8
  TOP w0.254: Q1.1@66.861,69.888 68.468,71.495 71.169,71.495 71.766,70.897 R5.2@71.766,70.885 v1(72.429,70.885) ; v1(76.722,72.79) 77.207,73.276 U2.5@77.738,73.276
  Mid-Layer 1 w0.254: v1(72.429,70.885) 74.847,70.885 76.722,72.76 v1(76.722,72.79)
REGOUT: C11.2 U2.40 | length 2.5
  TOP w0.254: U2.40@82.418,75.956 82.418,76.467 82.056,76.829 82.056,77.604 C11.2@82.525,78.073
RESET#: C33.1 J4.10 R26.1 TP1.1 U1.41 U4.10 | length 87.7
  TOP w0.254: v1(39.79,54.07) 39.813,54.093 C33.1@39.813,54.604 R26.1@39.813,56.153 ; J4.10@63.641,85.965 63.641,86.608 64.53,87.497 v1@69.788,87.497 ; U1.41@67.033,53.292 67.033,54.668 67.654,55.29 v1(69.788,55.29) 71.718,57.22 TP1.1@71.794,57.22 ; v1(69.788,66.059) 70.068,65.779 U4.10@78.221,65.779
  Mid-Layer 1 w0.254: v1(39.79,54.07) 64.784,54.07 65.343,54.629 69.127,54.629 v1(69.788,55.29)
  Mid-Layer 2 w0.254: v1(69.788,55.29) v1(69.788,66.059) v1(69.788,87.471)
RESET_OB#: ?.1 J2.4 J3.3 R8.1 U2.1 | length 31.2
  TOP w0.254: v1(77.156,75.866) 77.156,75.658 77.539,75.276 U2.1@77.738,75.276 ; v1(77.156,79.826) ?.1@78.553,79.826 ; v1(89.003,76.613) 89.498,77.108 89.6,77.108 92.752,73.956 R8.1@92.752,69.107 90.641,69.107 J2.4@90.413,69.336
  Mid-Layer 1 w0.254: v1@77.181,75.866 77.252,75.937 87.113,75.937 87.415,75.635 88.025,75.635 v1(89.003,76.613)
  Mid-Layer 2 w0.254: v1(77.156,75.866) v1(77.156,79.826)
RSH: J5.29 R44.1 R82.2 | length 50.8
  TOP w0.254: R82.2@75.085,39.798 75.085,39.121 v1(75.096,39.11) ; R44.1@113.313,45.88 113.425,45.767 113.323,45.666 v1(113.323,42.945) 117.718,42.945 118.759,43.987 ; 118.708,43.987 118.759,43.987 ; J5.29@119.737,43.987 118.759,43.987
  Mid-Layer 1 w0.254: v1(75.096,39.11) 75.579,38.627 107.913,38.627 112.231,42.945 v1(113.323,42.945)
RSL: J5.31 R48.1 R83.2 | length 53.2
  TOP w0.254: v1(76.087,38.068) R83.2@76.087,39.798 ; R48.1@113.287,47.72 113.287,47.659 112.511,46.882 v1(112.511,42.31) 117.895,42.31 118.759,41.447 J5.31@119.737,41.447
  Mid-Layer 1 w0.254: v1(76.087,38.068) 108.269,38.068 v1(112.511,42.31)
RSL_INT: J5.32 J5.36 J5.38 J5.40 R43.1 | length 14.1
  TOP w0.254: J5.32@125.197,41.447 127.446,41.447 129.503,39.389 129.503,34.741 132.437,31.807 132.437,31.68
RST#: R14.1 R17.2 U9.19 | length 14
  TOP w0.254: R17.2@34.406,82.623 R14.1@35.549,82.623 v1(36.184,81.988) ; v1(39.587,75.737) 39.587,74.492 40.857,73.223 U9.19@42.147,73.223
  Mid-Layer 2 w0.254: v1@36.184,81.96 36.184,79.14 v1(39.587,75.737)
RUN_IND: LD2.1 U2.18 | length 33.5
  TOP w0.254: U2.18@80.918,69.096 80.918,68.442 v1(81.142,68.218) ; v1(91.683,88.183) 93.105,89.605 LD2.1@93.105,89.808
  Mid-Layer 1 w0.254: v1(81.396,88.183) v1(91.683,88.183)
  Mid-Layer 2 w0.254: v1(81.142,68.218) 81.396,68.472 v1(81.396,88.183)
RX_LED: LD6.1 U9.23 | length 21.9
  TOP w0.254: U9.23@42.147,75.824 43.002,75.824 43.423,76.245 v1(44.947,76.245) ; v1(49.874,88.487) 50.981,89.594 LD6.1@50.981,89.808
  Mid-Layer 1 w0.254: v1(44.947,88.487) v1(49.874,88.487)
  Mid-Layer 2 w0.254: v1(44.947,76.245) v1(44.947,88.487)
S/S: J10.1 J10.3 T2.2 | length 7.7
  TOP w0.254: T2.2@30.469,47.059 30.469,46.882 31.307,46.044 31.307,43.428 J10.1@32.145,42.59 J10.3@32.145,40.05
SCK: J17.5 U8.6 | length 10.2
  TOP w0.254: v1(45.759,44.52) U8.6@47.325,44.52
  Mid-Layer 1 w0.254: v1(45.759,44.52) 46.801,43.479 51.246,43.479 J17.5@53.202,45.434
SDI: J17.3 U8.2 | length 12.1
  TOP w0.254: U8.2@42.415,45.79 43.067,45.79 43.6,45.257 v1(44.845,45.257)
  Mid-Layer 1 w0.254: v1(44.845,45.257) 50.077,45.257 52.795,47.974 J17.3@53.202,47.974
SDO: J17.1 U8.5 | length 10.2
  TOP w0.254: U8.5@47.325,43.25 48.147,43.25 48.807,43.911 v1(48.807,46.12)
  Mid-Layer 1 w0.254: v1(48.807,46.12) J17.1@53.202,50.514
SLC: J5.27 U1.9 | length 68.5
  TOP w0.254: v1@61.914,41.802 61.812,41.802 60.593,43.021 60.593,47.365 61.096,47.867 U1.9@62.108,47.867 ; v1(117.718,46.527) J5.27@119.737,46.527
  Mid-Layer 1 w0.254: v1@61.882,41.745 62.867,40.761 77.408,40.761 80.43,43.783 114.974,43.783 v1(117.718,46.527)
  other v1: 61.863,41.751
SLC_INT: J5.28 R89.2 | length 12.8
  TOP w0.254: J5.28@125.197,46.527 126.277,46.527 130.418,42.386 R89.2@136.313,42.386
SWCLK: J4.4 J6.3 R21.1 U4.13 | length 32.3
  TOP w0.254: J4.4@67.451,85.965 67.451,84.859 v1(67.709,84.601) ; R21.1@67.682,77.159 67.682,77.589 v1(67.709,77.616) ; J6.3@67.709,65.323 69.202,63.829 U4.13@78.221,63.829
  Mid-Layer 2 w0.254: J6.3@67.709,65.323 v1(67.709,77.616) v1(67.709,84.601)
SWCLK_OB: J3.4 U2.38 | length 6.1
  TOP w0.254: U2.38@83.418,75.956 83.426,75.964 83.426,77.202 v1(83.418,77.21) ; v1(87.441,77.21) 88.152,77.21 J3.4@88.228,77.134
  Mid-Layer 1 w0.254: v1(83.418,77.21) v1(87.441,77.21)
SWDIO: J4.2 J6.1 R13.2 U4.14 | length 35.2
  TOP w0.254: J6.1@67.709,62.783 68.106,63.179 U4.14@78.221,63.179 ; v1(68.543,75.737) 68.543,76.095 R13.2@68.642,76.194 ; v1(68.543,84.601) 68.721,84.779 J4.2@68.721,85.965
  Mid-Layer 2 w0.254: J6.1@67.709,62.783 67.756,62.783 69.026,64.053 69.026,66.491 68.543,66.974 v1(68.543,75.737) v1(68.543,84.601)
SWDIO_OB: J3.2 U2.39 | length 6.4
  TOP w0.254: U2.39@82.918,75.956 v1(82.918,76.702) ; v1(87.593,76.321) 88.05,75.864 J3.2@88.228,75.864
  Mid-Layer 1 w0.254: v1(82.918,76.702) 87.212,76.702 v1(87.593,76.321)
T_RESET#: R15.1 U2.27 U4.7 | length 9
  TOP w0.254: U4.7@83.961,65.779 84.724,65.779 85.129,65.373 R15.1@86.069,65.373 86.069,65.754 v1@86.222,65.907 ; U2.27@84.598,70.776 85.62,70.776 86.234,70.161 v1@86.234,69.564
  Mid-Layer 2 w0.254: v1@86.158,65.907 v1(86.158,69.564)
  other v1: 86.145,65.907
T_SWCLK: U2.25 U4.4 | length 7.3
  TOP w0.254: U4.4@83.961,63.829 v1(84.926,63.829) v1@85.002,63.829 ; U2.25@84.598,69.776 84.817,69.776 85.002,69.59 v1@85.002,69.26
  Mid-Layer 2 w0.254: v1(84.926,63.829) v1(84.926,69.26)
T_SWDIO: U2.26 U4.3 | length 9.7
  TOP w0.254: U4.3@83.996,63.214 U4.3@83.961,63.179 v1(85.551,63.179) v1@85.628,63.179 ; U2.26@84.598,70.276 85.358,70.276 v1@85.628,70.006
  Mid-Layer 2 w0.254: v1(85.551,63.179) v1(85.551,70.006)
TEMP: J5.7 J16.2 J16.6 R63.2 | length 52.3
  TOP w0.254: v1(113.041,70.905) R63.2@113.041,71.571
  TOP w0.406: R63.2@113.041,71.571 119.381,71.571 J5.7@119.737,71.927
  Mid-Layer 1 w0.254: v1(91.937,71.266) 103.341,71.266 103.702,70.905 v1(113.041,70.905)
  Mid-Layer 2 w0.254: J16.6@83.504,53.613 82.285,54.832 82.285,57.474 J16.2@83.504,58.693 83.504,59.938 88.558,64.992 90.87,64.992 91.937,66.059 v1(91.937,71.266)
TEMP_INT: J5.8 RT1.1 | length 13.4
  TOP w0.254: v1(125.197,70.809) J5.8@125.197,71.927 ; v1(133.948,72.054) 135.091,73.197 RT1.1@136.456,73.197
  BOTTOM w0.254: v1(125.197,70.809) 132.704,70.809 v1(133.948,72.054)
TX_LED: LD7.1 U9.22 | length 27.3
  TOP w0.254: U9.22@42.147,75.173 43.139,75.173 43.626,75.66 v1(44.409,75.66) ; v1(54.273,87.781) 56.162,89.67 LD7.1@56.162,89.834
  Mid-Layer 1 w0.254: v1(44.409,87.781) v1(54.273,87.781)
  Mid-Layer 2 w0.254: v1(44.409,75.66) v1(44.409,87.781)
U: J5.23 U1.12 | length 62
  TOP w0.254: U1.12@62.108,46.367 v1@63.616,46.367 ; v1(117.819,50.718) 118.708,51.607
  Mid-Layer 1 w0.254: v1(63.616,46.349) 64.708,45.257 66.892,45.257 69.838,42.311 76.596,42.311 79.16,44.876 89.676,44.876 90.362,45.561 112.765,45.561 v1@117.794,50.591
UART-RX: J14.1 J14.3 J14.5 J14.7 U9.1 | length 30.5
  TOP w0.254: U9.1@35.097,79.075 36.122,79.075 36.981,78.216 v1(36.981,77.124)
  Mid-Layer 2 w0.254: v1(36.981,77.124) 36.981,75.871 40.291,72.562 50.636,72.562 J14.1@52.973,70.225 J14.3@52.973,67.685 J14.5@52.973,65.145 J14.7@52.973,62.605
UART-TX: J15.1 J15.3 J15.5 J15.7 U9.5 | length 27.3
  TOP w0.254: U9.5@35.097,76.474 v1(37.631,76.473)
  Mid-Layer 2 w0.254: v1(37.631,76.473) 40.705,73.4 51.779,73.4 J15.7@52.973,74.594 J15.5@52.973,77.134 J15.3@52.973,79.674 J15.1@52.973,82.214
USB-D_N: R20.2 TVS2.5 U9.16 | length 14.7
  TOP w0.254: R20.2@39.067,82.623 38.787,82.343 38.787,81.045 ; TVS2.5@39.272,81.045 38.787,81.045 ; U9.16@42.147,71.272 41.472,71.272 41.365,71.165 40.095,71.165 38.787,72.473 38.787,81.045
USB-D_P: R19.2 TVS2.2 U9.15 | length 15.4
  TOP w0.254: TVS2.2@37.922,81.045 38.381,81.045 38.406,81.02 ; R19.2@38.127,82.623 38.406,82.343 38.406,81.02 ; U9.15@42.147,70.621 41.503,70.621 41.347,70.777 41.292,70.777 41.285,70.784 39.937,70.784 38.406,72.315 38.406,81.02
USB_N: CN3.A7 CN3.B7 R20.1 | length 3.7
  TOP w0.254: CN3.A7@38.347,85.544 38.347,84.947 38.914,84.379 ; R20.1@39.054,83.576 38.787,83.843 38.787,84.252 38.914,84.379 ; CN3.B7@39.347,85.544 39.347,84.811 38.914,84.379
USB_P: CN3.A6 CN3.B6 R19.1 | length 4.9
  TOP w0.254: 38.114,83.754 38.406,84.046 38.406,84.277 37.847,84.837 37.847,85.544 37.847,86.344 38.028,86.525 38.647,86.525 38.847,86.326 CN3.A6@38.847,85.544
V: J5.17 U1.11 | length 66.3
  TOP w0.254: U1.11@62.108,46.867 63.321,46.867 v1(63.59,47.136) ; v1(117.895,58.439) 118.683,59.227 J5.17@119.737,59.227
  Mid-Layer 1 w0.254: v1(72.404,57.906) 77.84,57.906 79.846,59.912 84.774,59.912 86.247,58.439 v1(117.895,58.439)
  Mid-Layer 2 w0.254: v1(63.59,47.136) 67.426,50.972 69.439,50.972 72.404,53.937 v1(72.404,57.906)
V-5V: C7.2 C8.2 U1.32 U1.35 | length 8.6
  TOP w0.254: U1.32@70.458,49.867 71.884,49.867 73.611,51.594 74.055,52.039 C8.2@74.055,52.219 ; U1.35@70.458,51.367 70.516,51.426 71.868,51.426 v1(72.023,51.581) C7.2@72.023,52.219
  BOTTOM w0.406: v1(72.023,51.581) v1(73.623,51.581)
V-USB: CN3.A4B9 CN3.B4A9 R14.2 | length 9.1
  TOP w0.305: R14.2@35.549,83.583 36.197,84.231 36.197,85.544 36.362,85.71 36.362,86.475 37.047,87.16 39.879,87.16 40.827,86.212 40.827,85.714 CN3.A4B9@40.997,85.544
VBAT: C1.2 C2.2 C3.2 C4.2 C5.2 C24.2 C25.2 C42.1 C43.2 J5.1 J5.3 J5.5 R3.2 R81.2 TB1.2 U1.29 U1.30 U3.4 U3.5 | length 78.1
  TOP w0.254: R81.2@65.775,40.103 66.534,40.103 v1(66.537,40.1) ; 116.397,81.629 116.397,84.804 118.175,86.582 R3.2@118.355,86.582
  TOP w0.406: C43.2@73.567,42.64 73.572,42.645 v1(73.572,43.148)
  TOP w0.508: v1(78.17,48.584) 88.609,48.584 89.346,49.321 97.55,49.321 98.541,50.311 106.618,50.311 113.806,57.499 113.806,69.437 113.298,69.945 109.031,69.945
  BOTTOM w0.406: v1(66.537,40.1) 69.077,42.64 73.064,42.64 v1(73.572,43.148) 76.722,46.298 76.722,47.314 77.357,47.949
  other v1: 77.713,48.279 77.713,48.889
VBAT_INT: J5.2 J5.4 J5.6 Q2.1 Q2.2 Q2.5 Q2.6 Q3.1 Q3.2 Q3.5 Q3.6 Q4.1 Q4.2 Q4.5 Q4.6
  other v1: 140.781,42.234 141.797,42.234 142.822,42.229 140.781,42.844 141.797,42.844 142.838,42.844 140.781,57.932 141.797,57.932 142.822,57.927 140.781,58.541 141.797,58.541 142.838,58.541 142.822,73.494 140.781,73.499 141.797,73.499 140.781,74.108 141.797,74.108 142.838,74.108 122.481,75.351 123.09,75.351 122.481,76.367 123.09,76.367 123.095,77.392 122.481,77.408 122.481,78.424 123.09,78.424 123.095,79.45 122.481,79.466
VCC-3.3V: C19.1 C34.1 C35.1 C36.1 C37.1 C38.1 C40.2 J3.1 M1.2 R1.1 R7.1 R8.2 R15.2 R16.2 R22.1 R23.2 R25.1 U2.4 U2.23 U2.34 U2.44 U2.45 U4.2 U10.1 U10.2 U10.4 | length 65.5
  TOP w0.254: C34.1@76.011,73.143 76.643,73.776 U2.4@77.738,73.776 ; U2.45@79.918,75.956 79.918,77.593 C37.1@79.513,77.997 79.16,78.35 v1(79.16,78.429) 79.16,78.533 C38.1@79.513,78.886 80.418,77.982 U2.44@80.418,75.956 ; C35.1@83.227,67.786 83.418,67.977 U2.23@83.418,69.096 ; U2.34@84.598,74.276 85.876,74.276 C36.1@86.069,74.469 ; v1@93.638,73.501 v1(93.74,73.501) ; v1(95.797,72.46) 95.815,72.478 U10.4@95.815,72.879
  TOP w0.305: v1(83.227,67.202) C35.1@83.227,67.786 ; U4.2@83.961,62.529 85.053,62.529 85.917,61.665 C19.1@85.917,61.535 86.041,61.535 86.603,62.097 v1(86.603,63.88) R15.2@86.069,64.413 ; C36.1@86.069,74.469 v1(86.653,74.469) ; R7.1@86.069,77.893 v1(86.653,77.893) ; v1(94.121,79.074) R23.2@95.648,79.074
  TOP w0.406: v1(64.05,77.159) R16.2@64.583,77.159 ; R1.1@73.395,81.177 75.065,81.177 M1.2@75.263,80.979 75.442,80.979 v1(75.833,80.588) ; v1(75.427,73.143) C34.1@76.011,73.143 ; J3.1@89.498,75.864 v1(89.994,75.368) ; v1(92.902,86.582) R22.1@93.514,86.582 ; R8.2@93.712,69.107 v1(93.712,69.666) ; v1(97.55,86.582) R25.1@98.162,86.582
  Mid-Layer 1 w0.254: v1(64.05,77.159) 68.066,73.143 v1(75.427,73.143)
  Mid-Layer 2 w0.254: v1(93.712,69.666) 93.003,70.375 93.003,73.095 93.41,73.501 v1(93.74,73.501) ; v1(93.74,74.009) 94.248,74.009 v1(95.797,72.46)
  BOTTOM w0.305: v1(86.603,63.88) 86.704,63.982 86.704,66.923
  BOTTOM w0.406: 92.216,81.071 92.902,81.756 v1(92.902,86.582) ; 94.197,79.314 97.55,82.667 v1(97.55,86.582)
VCC-5V: C18.1 C21.2 C22.2 C23.1 C26.2 C29.1 C30.1 D2.2 FB1.1 FP2.1 HDR1.1 HDR1.2 J4.1 L1.2 P1.1 pad.@30.543,62.783 Q8.2 R9.2 R11.2 R12.2 R13.1 R24.2 R52.2 R63.1 R64.2 R66.2 R68.2 R73.1 R74.1 R75.1 R76.1 R87.1 R88.1 SW2.3 SW2.4 TB3.1 TB5.1 U4.15 U8.8 U9.4 U9.20 | length 481.2
  TOP w0.254: D2.2@110.275,59.052 111.266,60.043 111.266,63.598 R9.2@110.761,64.103 C21.2@110.761,65.12
  TOP w0.305: C18.1@76.493,61.535 76.493,61.546 77.501,62.554 78.196,62.554 U4.15@78.221,62.529
  TOP w0.406: pad.@30.543,62.783 SW2.4@30.543,63.037 30.543,65.323 ; v1(32.78,77.124) 33.256,77.124 C29.1@33.263,77.131 33.27,77.124 U9.4@35.097,77.124 ; R88.1@39.59,44.495 v1(39.59,46.196) R87.1@39.59,47.06 ; v1(39.813,57.286) R24.2@39.813,57.804 ; U9.20@42.147,73.873 43.835,73.873 C30.1@43.905,73.943 44.409,73.943 v1(44.413,73.938) ; v1(42.584,29.661) R76.1@42.584,30.222 ; v1(42.584,32.252) R75.1@42.584,32.813 ; v1(42.584,34.665) R74.1@42.584,35.226 ; R73.1@43.956,48.66 v1(43.956,49.178) ; v1(46.75,49.178) C26.2@46.75,48.66 47.283,48.127 47.283,47.949 47.325,47.907 U8.8@47.325,47.06 ; R11.2@52.386,86.608 v1(54.484,86.608) R12.2@56.582,86.608 ; v1(67.149,76.194) R13.1@67.682,76.194 ; J4.1@68.721,90.215 v1(70.242,90.215) ; v1(75.909,61.535) C18.1@76.493,61.535 ; R64.2@76.973,24.276 v1(77.586,24.276) ; R66.2@85.454,24.251 v1(86.067,24.251) ; P1.1@91.384,51.705 v1(91.384,53.226) ; R68.2@94.245,24.251 v1(94.858,24.251) ; v1(97.944,40.329) FB1.1@97.944,41.193 ; C22.2@104.19,53.969 104.216,53.943 108.675,53.943 110.275,55.544 D2.2@110.275,59.052 ; R52.2@106.262,25.996 v1(107.126,25.996) 108.039,25.996 Q8.2@108.286,26.242 ; v1@111.52,71.571 R63.1@112.081,71.571
  BOTTOM w0.406: v1(32.78,77.124) 36.514,73.39 36.514,60.7 ; 39.155,60.293 39.254,60.194 39.254,57.832 40.502,56.585 40.502,47.108 v1(39.59,46.196) ; v1(43.956,49.178) 43.956,60.293 ; 44.149,49.244 46.684,49.244 v1(46.75,49.178) ; 44.413,60.293 v1(44.413,73.938) ; v1(54.484,86.608) 59.069,82.023 59.069,66.313 58.129,65.373 58.129,60.293 ; v1(67.149,76.194) 67.149,68.495 69.051,66.593 69.051,58.82 ; v1(70.242,90.215) 72.125,88.332 72.125,72.384 74.334,70.174 74.334,61.792 ; v1(77.586,24.276) 77.611,24.251 v1(86.067,24.251) ; 87.39,61.792 87.39,25.574 v1(86.067,24.251) ; v1(91.384,53.226) 91.384,61.671 91.505,61.792 ; v1(94.858,24.251) v1(86.067,24.251) ; v1(97.944,40.329) 97.944,44.719 v1(104.856,51.632) ; 99.785,59.836 99.785,59.877 v1(111.474,71.566) ; v1(105.39,51.632) 105.703,51.632 114.314,43.021 114.314,33.184 v1(107.126,25.996)
  BOTTOM w0.508: v1(42.584,34.665) v1(42.584,32.252) v1(42.584,29.661) 43.727,28.518 50.204,28.518 ; TB3.1@43.626,23.438 43.626,25.114 44.87,26.359 49.366,26.359 50.204,27.197 50.204,28.518 ; TB5.1@55.284,23.438 55.284,24.835 51.601,28.518 50.204,28.518
  BOTTOM w0.762: 50.204,28.518 50.204,60.293 ; v1(94.859,69.463) v1(94.859,68.904) 94.859,62.266 95.334,61.792
  BOTTOM w1.524: HDR1.2@21.659,72.87 23.446,71.083 23.446,71.076 v1(30.519,64.002) 34.228,60.293 39.155,60.293 43.956,60.293 ; HDR1.2@21.68,72.892 HDR1.1@21.68,75.432 ; 44.413,60.293 50.204,60.293 ; 50.611,60.293 58.129,60.293 59.602,58.82 69.051,58.82 71.363,58.82 74.334,61.792 87.39,61.792 91.505,61.792 95.334,61.792 97.829,61.792 99.785,59.836 105.145,54.477 105.145,51.861
  other v1: 104.856,52.165 105.39,52.165 104.856,52.699 105.39,52.699
VCC-USB: R86.1 U2.13 | length 15.1
  TOP w0.254: v1(77.715,69.096) U2.13@78.418,69.096 ; v1(77.715,82.648) R86.1@78.449,82.648 R86.1@78.396,82.595
  Mid-Layer 2 w0.254: v1@77.662,82.595 v1@77.664,82.593 ; v1(77.715,69.096) v1(77.715,82.648)
VCP: C43.1 R84.1 U1.21 | length 30.8
  TOP w0.254: v1(67.502,43.707) 67.533,43.738 U1.21@67.533,44.942 ; v3@72.607,43.606 C43.1@72.607,42.64 72.607,39.948 75.173,37.383 88.988,37.383 R84.1@91.223,39.618
  BOTTOM w0.406: v1(67.502,43.707) 72.506,43.707 v3(72.633,43.987)
VCP_MON: C46.2 J12.1 J12.3 R84.2 R85.2 | length 12.3
  TOP w0.254: J12.1@83.605,39.999 J12.3@83.605,42.539 90.161,42.539 C46.2@90.263,42.641 90.263,41.142 R84.2@90.263,39.618
VDD: C6.2 U1.33 | length 3.7
  TOP w0.254: U1.33@70.458,50.367 71.773,50.367 73.039,51.633 C6.2@73.039,52.219
VDDA: C52.2 C53.2 C60.2 FB1.2 R56.2 R57.2 U5.8 U6.7 U7.5 | length 46.3
  TOP w0.406: R57.2@93.918,37.492 94.038,37.492 v1(94.553,36.976) ; v1(99.544,40.329) 99.544,41.332 98.019,42.857 C52.2@98.019,43.148 98.019,44.964 99.201,46.146 U6.7@99.946,46.146 ; v1(100.242,36.976) 100.758,37.492 ; U5.8@104.818,31.296 106.69,31.296 C53.2@106.935,31.541 106.935,31.63 v1(105.983,32.582) ; U7.5@110.184,37.596 112.361,37.596 C60.2@112.536,37.421 ; 112.449,37.389 v1(112.964,36.874)
  BOTTOM w0.406: v1(94.553,36.976) v1(100.242,36.976) ; v1(99.544,40.329) 99.544,37.675 v1(100.242,36.976) ; v1(105.983,32.582) 104.637,32.582 v1(100.242,36.976) ; v1(112.964,36.874) 112.125,37.713 100.979,37.713 v1(100.242,36.976)
W: J5.11 U1.10 | length 70.2
  TOP w0.254: U1.10@62.108,47.367 62.958,47.367 v1(63.438,47.847) ; v1(117.032,65.196) 118.683,66.847 J5.11@119.737,66.847
  Mid-Layer 1 w0.254: v1(71.769,61.919) 72.048,62.198 93.359,62.198 95.01,63.849 115.686,63.849 v1(117.032,65.196)
  Mid-Layer 2 w0.254: v1(63.438,47.847) 67.095,51.505 69.058,51.505 71.769,54.216 v1(71.769,61.919)
WP: J17.9 R88.2 U8.3 | length 14.4
  TOP w0.254: R88.2@40.55,44.495 40.575,44.52 U8.3@42.415,44.52 43.145,44.52 v1(43.707,43.959)
  Mid-Layer 1 w0.254: v1(43.707,43.959) 45.66,42.005 51.551,42.005 J17.9@53.202,40.354
XIN: C9.2 U1.42 Y1.1 | length 7.8
  TOP w0.254: U1.42@66.533,53.292 66.533,55.979 Y1.1@68.333,57.779 C9.2@68.333,60.319
XOUT: C10.2 U1.43 Y1.2 | length 7.8
  TOP w0.254: C10.2@64.233,60.319 Y1.2@64.233,57.779 66.033,55.979 U1.43@66.033,53.292
pads on no net: CN2.5 CN2.6 CN2.A8 CN2.B8 CN3.5 CN3.6 CN3.A8 CN3.B8 J3.6 J3.7 J3.8 J3.9 J4.6 J4.7 J4.8 SW1.3 SW3.3 T1.3 T1.4 T2.3 T2.4 TVS1.3 TVS1.6 TVS2.3 TVS2.6 U1.8 U1.38 U2.6 U2.7 U2.8 U2.9 U2.10 U2.11 U2.12 U2.14 U2.15 U2.16 U2.19 U2.20 U2.21 U2.22 U2.28 U2.30 U2.31 U2.35 U2.36 U4.1 U4.5 U4.6 U4.11 U4.12 U4.16 U6.1 U6.5 U6.8 U9.2 U9.3 U9.6 U9.8 U9.9 U9.10 U9.11 U9.12 U9.13 U9.14 U9.24 U9.27 U9.28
